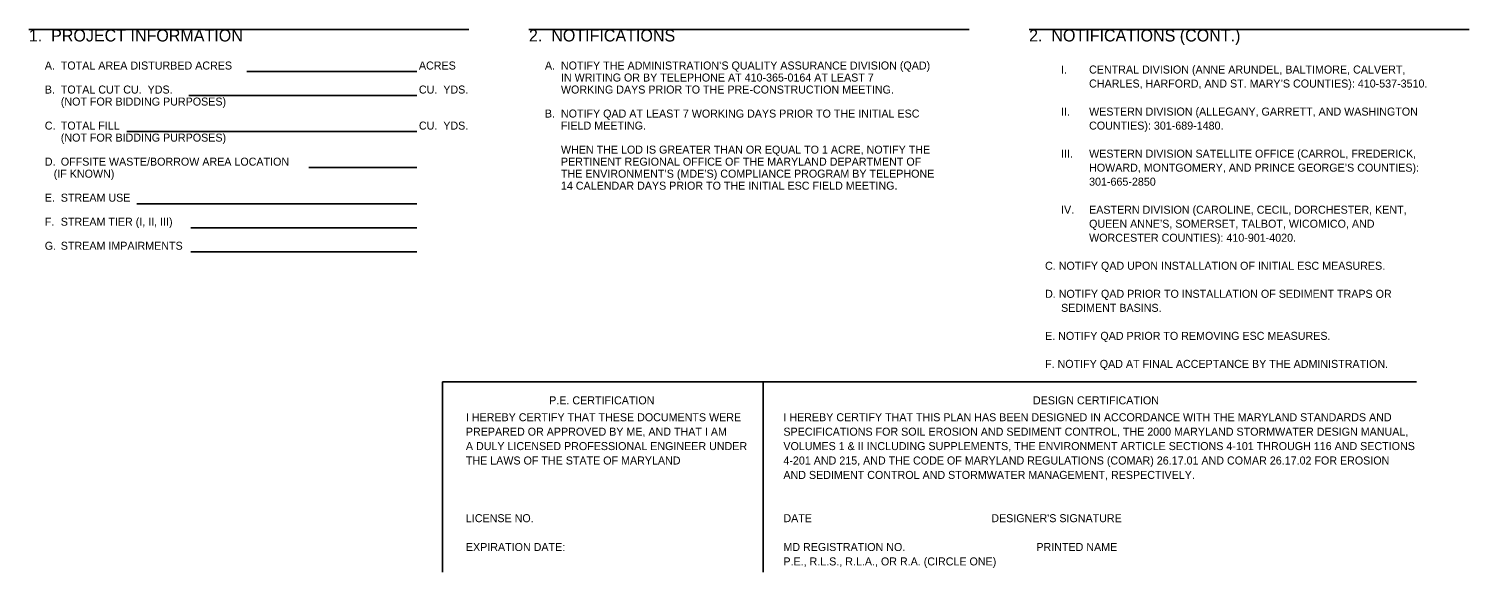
# Model space of a CAD drawing. Extents: x 1.3 to 34, y 0 to 22.5.
# Drawn here: x 2 to 20, y 0.75 to 7.53 of the extents above; entities that cross this region are included whole.
import ezdxf

# ---------------------------------------------------------------- set-up
doc = ezdxf.new("R2010")
doc.units = 0
for name, color, linetype in [('ANNO-CERT', 7, 'Continuous'), ('ANNO-NOTE', 7, 'Continuous'), ('BORD-LINE', 7, 'Continuous'), ('USER-LINE', 7, 'Continuous')]:
    doc.layers.add(name, color=color, linetype=linetype)

msp = doc.modelspace()

# ---------------------------------------------------------------- linework, layer by layer
at = {"layer": 'ANNO-NOTE'}
for p, q in [((4.725, 7), (6.85, 7)), ((4, 6.7), (6.85, 6.7)), ((3.225, 6.25), (6.85, 6.25)), ((5.5, 5.8), (6.85, 5.8)), ((3.35, 5.35), (6.85, 5.35)), ((4.025, 5.05), (6.85, 5.05)), ((4.025, 4.75), (6.85, 4.75))]:
    msp.add_line(p, q, dxfattribs=at)
at = {"layer": 'BORD-LINE'}
for p, q in [((7.17, 0.75), (7.17, 3.125)), ((7.17, 3.125), (11.175, 3.125)), ((11.175, 3.125), (19.341, 3.125)), ((11.175, 3.125), (11.175, 0.75))]:
    msp.add_line(p, q, dxfattribs=at)
at = {"layer": 'USER-LINE'}
for p, q in [((7.5, 7.525), (2, 7.525)), ((13.75, 7.525), (8.25, 7.525)), ((20, 7.525), (14.5, 7.525))]:
    msp.add_line(p, q, dxfattribs=at)

# ---------------------------------------------------------------- texts
at = {"layer": 'ANNO-CERT'}
for s, p in [('  P.E. CERTIFICATION  ', (8.429, 2.845)), ('  DESIGN CERTIFICATION  ', (14.474, 2.845)), ('I HEREBY CERTIFY THAT THESE DOCUMENTS WERE ', (7.462, 2.634)), ('I HEREBY CERTIFY THAT THIS PLAN HAS BEEN DESIGNED IN ACCORDANCE WITH THE MARYLAND STANDARDS AND ', (11.43, 2.634)), ('PREPARED OR APPROVED BY ME, AND THAT I AM ', (7.462, 2.454)), ('SPECIFICATIONS FOR SOIL EROSION AND SEDIMENT CONTROL, THE 2000 MARYLAND STORMWATER DESIGN MANUAL, ', (11.43, 2.454)), ('A DULY LICENSED PROFESSIONAL ENGINEER UNDER ', (7.462, 2.274)), ('VOLUMES 1 & II INCLUDING SUPPLEMENTS, THE ENVIRONMENT ARTICLE SECTIONS 4-101 THROUGH 116 AND SECTIONS ', (11.43, 2.274)), ('THE LAWS OF THE STATE OF MARYLAND', (7.462, 2.094)), ('4-201 AND 215, AND THE CODE OF MARYLAND REGULATIONS (COMAR) 26.17.01 AND COMAR 26.17.02 FOR EROSION ', (11.43, 2.094)), ('AND SEDIMENT CONTROL AND STORMWATER MANAGEMENT, RESPECTIVELY.', (11.43, 1.914)), ('LICENSE NO. ', (7.462, 1.374)), ('DATE ', (11.43, 1.374)), (" DESIGNER'S SIGNATURE ", (13.991, 1.374)), ('EXPIRATION DATE: ', (7.462, 1.014)), ('MD REGISTRATION NO. ', (11.43, 1.014)), (' PRINTED NAME ', (14.554, 1.014)), ('P.E., R.L.S., R.L.A., OR R.A. (CIRCLE ONE)', (11.43, 0.834))]:
    msp.add_text(s, height=0.1, rotation=360, dxfattribs=at).set_placement(p)
at = {"layer": 'ANNO-NOTE'}
for s, height, p in [('1.  PROJECT INFORMATION', 0.15, (2, 7.375)), ('2.  NOTIFICATIONS', 0.15, (8.25, 7.375)), ('2.  NOTIFICATIONS (CONT.)', 0.15, (14.5, 7.375)), ('A.', 0.1, (2.2, 7.025)), ('TOTAL AREA DISTURBED ACRES', 0.1, (2.4, 7.025)), ('ACRES', 0.1, (6.875, 7.025)), ('A.', 0.1, (8.45, 7.025)), ('NOTIFY THE ADMINISTRATION’S QUALITY ASSURANCE DIVISION (QAD) ', 0.1, (8.65, 7.025)), ('I.', 0.1, (14.9, 6.975)), ('CENTRAL DIVISION (ANNE ARUNDEL, BALTIMORE, CALVERT, ', 0.1, (15.25, 6.975)), ('IN WRITING OR BY TELEPHONE AT 410-365-0164 AT LEAST 7 ', 0.1, (8.65, 6.875)), ('CHARLES, HARFORD, AND ST. MARY’S COUNTIES): 410-537-3510.', 0.1, (15.25, 6.8)), ('B.', 0.1, (2.2, 6.725)), ('TOTAL CUT CU.  YDS.', 0.1, (2.4, 6.725)), ('(NOT FOR BIDDING PURPOSES)', 0.1, (2.4, 6.575)), ('CU.  YDS.', 0.1, (6.875, 6.725)), ('WORKING DAYS PRIOR TO THE PRE-CONSTRUCTION MEETING.', 0.1, (8.65, 6.725)), ('B.', 0.1, (8.45, 6.425)), ('NOTIFY QAD AT LEAST 7 WORKING DAYS PRIOR TO THE INITIAL ESC ', 0.1, (8.65, 6.425)), ('II.', 0.1, (14.9, 6.45)), ('WESTERN DIVISION (ALLEGANY, GARRETT, AND WASHINGTON ', 0.1, (15.25, 6.45)), ('C.', 0.1, (2.2, 6.275)), ('TOTAL FILL', 0.1, (2.4, 6.275)), ('CU.  YDS.', 0.1, (6.875, 6.275)), ('FIELD MEETING.', 0.1, (8.65, 6.275)), ('COUNTIES): 301-689-1480.', 0.1, (15.25, 6.275)), ('(NOT FOR BIDDING PURPOSES)', 0.1, (2.4, 6.125)), ('WHEN THE LOD IS GREATER THAN OR EQUAL TO 1 ACRE, NOTIFY THE ', 0.1, (8.65, 5.975)), ('III.', 0.1, (14.9, 5.925)), ('WESTERN DIVISION SATELLITE OFFICE (CARROL, FREDERICK, ', 0.1, (15.25, 5.925)), ('D.', 0.1, (2.2, 5.825)), ('   (IF KNOWN)', 0.1, (2.2, 5.675)), ('OFFSITE WASTE/BORROW AREA LOCATION', 0.1, (2.4, 5.825)), ('THE ENVIRONMENT’S (MDE’S) COMPLIANCE PROGRAM BY TELEPHONE ', 0.1, (8.65, 5.675)), ('PERTINENT REGIONAL OFFICE OF THE MARYLAND DEPARTMENT OF ', 0.1, (8.65, 5.825)), ('HOWARD, MONTGOMERY, AND PRINCE GEORGE’S COUNTIES): ', 0.1, (15.25, 5.75)), ('14 CALENDAR DAYS PRIOR TO THE INITIAL ESC FIELD MEETING.', 0.1, (8.65, 5.525)), ('301-665-2850', 0.1, (15.25, 5.575)), ('E.', 0.1, (2.2, 5.375)), ('STREAM USE ', 0.1, (2.4, 5.375)), ('IV.', 0.1, (14.9, 5.225)), ('EASTERN DIVISION (CAROLINE, CECIL, DORCHESTER, KENT, ', 0.1, (15.25, 5.225)), ('F.', 0.1, (2.2, 5.075)), ('STREAM TIER (I, II, III)    ', 0.1, (2.4, 5.075)), ('QUEEN ANNE’S, SOMERSET, TALBOT, WICOMICO, AND ', 0.1, (15.25, 5.05)), ('G.', 0.1, (2.2, 4.775)), ('STREAM IMPAIRMENTS ', 0.1, (2.4, 4.775)), ('WORCESTER COUNTIES): 410-901-4020.', 0.1, (15.25, 4.875)), ('C. NOTIFY QAD UPON INSTALLATION OF INITIAL ESC MEASURES.', 0.1, (14.7, 4.525)), ('D. NOTIFY QAD PRIOR TO INSTALLATION OF SEDIMENT TRAPS OR ', 0.1, (14.7, 4.175)), ('SEDIMENT BASINS.', 0.1, (14.9, 4)), ('E. NOTIFY QAD PRIOR TO REMOVING ESC MEASURES.', 0.1, (14.7, 3.65)), ('F. NOTIFY QAD AT FINAL ACCEPTANCE BY THE ADMINISTRATION.', 0.1, (14.7, 3.3))]:
    msp.add_text(s, height=height, dxfattribs=at).set_placement(p)

doc.saveas('drawing.dxf')
